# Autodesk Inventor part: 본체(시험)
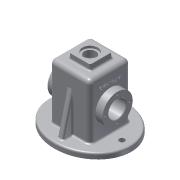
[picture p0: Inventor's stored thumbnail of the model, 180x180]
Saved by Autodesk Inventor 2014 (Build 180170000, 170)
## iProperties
Created: 2017-07
Part Number: 본체(시험)
Material: 알루미늄 6061
Document SubType Name: Modeling
Designer: 702-12
Density: 2.71 g/cm^3
Appearance: 알루미늄 - 평지
Mass: 893.713 g
Surface Area: 987.976 cm^2
Volume: 329.783 cm^3
Author: 702-12
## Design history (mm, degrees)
sketch "스케치1" dims "d0" = 75, "d1" = 65
  geometry: 2 further points; 1 other entity
  constraints: 1 coincident, 2 other
extrude "돌출1" new body sketch "스케치1" distance "d2" = 10; taper "d3" = 0 deg
sketch "스케치2"
  geometry: L1 (-37, -37)-(37, -37); L2 (37, -37)-(37, 37); L3 (37, 37)-(-37, 37); L4 (-37, 37)-(-37, -37); L5 (-37, -37)-(37, 37); L6 (37, -37)-(-37, 37); 1 further point; 1 other entity
  constraints: 12 end point, 2 midpoint, 2 parallel, 1 horizontal, 1 perpendicular, 1 other
  dimensions: "d4" = 74 distance of L3.end L2.end; "d5" = 74 distance of L2.end L1.end
extrude "돌출2" join sketch "스케치2" distance "d6" = 100; taper "d7" = 0 deg
sketch "스케치3"
  geometry: L1 (0, 74)-(-100, 74) reference; L2 (10, -28)-(10, 102) reference; C1 r 27.5 at (-45, 37); 1 further point
  constraints: 1 centre point
  dimensions: "d8" = 55 diameter of C1; "d9" = 55 distance from line of C1.centre L2; "d10" = 37 distance from line of L1 C1.centre
extrude "돌출3" join sketch "스케치3" distance "d11" = 13; taper "d12" = 0 deg
node "작업 평면1"
sketch "스케치4"
  geometry: L1 (65, 10)-(65, 0) reference; L2 (65, 0)-(-65, 0) reference; L3 (-65, 0)-(-65, 10) reference; L4 (-65, 10)-(-37, 10) reference; L5 (-37, 10)-(-37, 110) reference; L6 (-37, 110)-(37, 110) reference; L7 (37, 110)-(37, 10) reference; L8 (37, 10)-(65, 10) reference; L9 (-55, 10)-(-37, 82.194); L10 (-55, 10)-(8.14, 10); L11 (-37, 82.194)-(-37, 10); L12 (-55, 10)-(-37, 10); 1 further point
  constraints: 8 end point, 2 point on line, 1 collinear, 1 horizontal, 1 perpendicular
  dimensions: "d14" = 76 deg angle of L10 L9; "d15" = 10 distance of L3.end L9.start
extrude "돌출4" join sketch "스케치4" stored distance "d16" = 10; taper "d17" = 0 deg
node "작업 평면2"
sketch "스케치7"
  geometry: L1 (-32, -105)-(32, -105); L2 (32, -105)-(32, 105); L3 (32, 105)-(-32, 105); L4 (-32, 105)-(-32, -105); L5 (-32, -105)-(32, 105); L6 (32, -105)-(-32, 105); L7 (37, 110)-(-37, 110) reference; L8 (37, 10)-(37, 110) reference; 1 further point
  constraints: 12 end point, 2 midpoint, 2 parallel, 1 horizontal, 1 perpendicular
  dimensions: "d26" = 5 distance between parallel lines of L7 L3; "d27" = 5 distance between parallel lines of L8 L2
extrude "돌출7" cut sketch "스케치7" stored distance "d28" = 64; taper "d29" = 0 deg
sketch "스케치8"
  geometry: L1 (-37, 27.5)-(-50, 27.5) reference; L2 (-50, 27.5)-(-50, 82.5) reference; L3 (-50, 82.5)-(-37, 82.5) reference; L4 (-37, 82.5)-(-37, 110) reference; L5 (-37, 110)-(37, 110) reference; L6 (37, 110)-(37, 82.5) reference; L7 (37, 82.5)-(50, 82.5) reference; L8 (50, 82.5)-(50, 27.5) reference; L9 (50, 27.5)-(37, 27.5) reference; L10 (37, 27.5)-(37, 10) reference; L11 (37, 10)-(75, 10) reference; L12 (75, 10)-(75, 0) reference; L13 (75, 0)-(32, 0) reference; L14 (32, 0)-(32, 105) reference; L15 (32, 105)-(-32, 105) reference; L16 (-32, 105)-(-32, 0) reference; L17 (-32, 0)-(-75, 0) reference; L18 (-75, 0)-(-75, 10) reference; L19 (-75, 10)-(-37, 10) reference; L20 (-37, 10)-(-37, 27.5) reference; L21 (50, 55)-(-50, 55); L22 (32, 55)-(32, 82.5); L23 (32, 82.5)-(25, 75.5); L24 (32, 82.5)-(70.891, 82.5); L25 (25, 75.5)-(25, 55); L26 (0, 0)-(0, 105); L27 (-32, 82.5)-(-25, 75.5); L28 (-25, 75.5)-(-25, 55); L29 (-32, 55)-(-32, 82.5)
  constraints: 18 end point, 4 point on line, 4 symmetric about line, 3 midpoint, 1 horizontal, 1 perpendicular
  dimensions: "d31" = 27.5 distance of L22.start L22.end; "d32" = 135 deg angle of L23 L24
revolve "회전1" sketch "스케치8" stored, may be unused: angle "d34" = 90 deg
sketch "스케치10"
  geometry: C1 r 27.5 at (0, 0) reference; C2 r 16 at (0, 0); 1 further point
  constraints: 1 centre point, 1 coincident
  dimensions: "d38" = 32 diameter of C2
extrude "돌출9" cut sketch "스케치10" distance "d39" = 120; taper "d40" = 0 deg
sketch "스케치11"
  geometry: 5 further points
hole "구멍1" sketch "스케치11" at (-22.5, 0), (0, 22.5), (22.5, 0), (0, -22.5) diameter "d42" = 3.242; stored, may be unused: countersink angle "d46" = 90 deg, drill point angle "d48" = 118 deg; dims "d43" = 8, "d44" = 4, "d45" = 2, "d47" = 10
fillet "모깎기1" dims "d49" = 8
fillet "모깎기2" dims "d50" = 8
fillet "모깎기5" dims "d53" = 3
fillet "모깎기6" dims "d54" = 3
fillet "모깎기7" dims "d55" = 3
fillet "모깎기8" dims "d56" = 3
fillet "모깎기9" dims "d57" = 3
sketch "스케치12"
  geometry: L1 (40, -29)-(40, 29) reference; L2 (29, 40)-(8, 40) reference; L3 (8, 40)-(8, 51.16) reference; L4 (2, 57.344)-(-2, 57.344) reference; L5 (-8, 51.16)-(-8, 40) reference; L6 (-8, 40)-(-29, 40) reference; L7 (-40, 29)-(-40, -29) reference; L8 (-29, -40)-(-8, -40) reference; L9 (-8, -40)-(-8, -51.16) reference; L10 (-2, -57.344)-(2, -57.344) reference; L11 (8, -51.16)-(8, -40) reference; L12 (8, -40)-(29, -40) reference; L13 (-32, -32)-(32, -32) reference; L14 (32, -32)-(32, 32) reference; L15 (32, 32)-(-32, 32) reference; L16 (-32, 32)-(-32, -32) reference; L17 (0, 0)-(-58, 0); L18 (0, 0)-(58, 0); C1 r 5 at (-58, 0); C2 r 5 at (58, 0); A1 r 11 centre (29, -29) between (29, -40) and (40, -29) reference; A2 r 11 centre (29, 29) between (40, 29) and (29, 40) reference; A3 r 11 centre (-29, 29) between (-29, 40) and (-40, 29) reference; A4 r 11 centre (-29, -29) between (-40, -29) and (-29, -40) reference; 1 further point
  constraints: 4 end point, 2 centre point, 2 coincident, 1 collinear, 1 perpendicular, 5 other
  dimensions: "d58" = 58 distance of L17.start L17.end; "d59" = 10 diameter of C1; "d60" = 58 distance of L17.start L18.end; "d61" = 10 diameter of C2
extrude "돌출10" cut sketch "스케치12" distance "d62" = 120; taper "d63" = 0 deg
fillet "모깎기12" dims "d66" = 0.5
chamfer "모따기1" distance "d67" = 1; stored, may be unused: second distance "d68" = 2, angle "d69" = 45 deg
node "작업 평면3"
sketch "스케치13"
  geometry: L1 (-72, 10)-(-63, 10) reference; L2 (-63, 10)-(-63, 0) reference; L3 (-63, 0)-(-75, 0) reference; L4 (-75, 0)-(-75, 7) reference; L5 (75, 7)-(75, 0) reference; L6 (75, 0)-(63, 0) reference; L7 (63, 0)-(63, 10) reference; L8 (63, 10)-(72, 10) reference; L9 (39.026, 32.5)-(40, 30.879) reference; L10 (40, 30.879)-(50, 30.879) reference; L11 (50, 30.879)-(50, 27.5) reference; L12 (50, 27.5)-(37.5, 27.5) reference; L13 (37, 27)-(37, 13) reference; L14 (40, 10)-(53, 10) reference; L15 (53, 10)-(53, 0) reference; L16 (53, 0)-(32, 0) reference; L17 (32, 0)-(32, 27.293) reference; L18 (31.854, 27.646)-(25.146, 34.354) reference; L19 (25, 34.707)-(25, 39) reference; L20 (25, 39)-(49, 39) reference; L21 (49, 39)-(50, 38) reference; L22 (50, 38)-(50, 34.121) reference; L23 (50, 34.121)-(40, 34.121) reference; L24 (40, 34.121)-(39.026, 32.5) reference; L25 (-40, 30.879)-(-39.026, 32.5) reference; L26 (-39.026, 32.5)-(-40, 34.121) reference; L27 (-40, 34.121)-(-50, 34.121) reference; L28 (-50, 34.121)-(-50, 38) reference; L29 (-50, 38)-(-49, 39) reference; L30 (-49, 39)-(-25, 39) reference; L31 (-25, 39)-(-25, 34.707) reference; L32 (-25.146, 34.354)-(-31.854, 27.646) reference; L33 (-32, 27.293)-(-32, 0) reference; L34 (-32, 0)-(-53, 0) reference; L35 (-53, 0)-(-53, 10) reference; L36 (-53, 10)-(-40, 10) reference; L37 (-37, 13)-(-37, 27) reference; L38 (-37.5, 27.5)-(-50, 27.5) reference; L39 (-50, 27.5)-(-50, 30.879) reference; L40 (-50, 30.879)-(-40, 30.879) reference; L41 (-40, 75.879)-(-39.026, 77.5) reference; L42 (-39.026, 77.5)-(-40, 79.121) reference; L43 (-40, 79.121)-(-50, 79.121) reference; L44 (-50, 79.121)-(-50, 82.5) reference; L45 (-50, 82.5)-(-37.5, 82.5) reference; L46 (-37, 83)-(-37, 102) reference; L47 (-29, 110)-(29, 110) reference; L48 (37, 102)-(37, 83) reference; L49 (37.5, 82.5)-(50, 82.5) reference; L50 (50, 82.5)-(50, 79.121) reference; L51 (50, 79.121)-(40, 79.121) reference; L52 (40, 79.121)-(39.026, 77.5) reference; L53 (39.026, 77.5)-(40, 75.879) reference; L54 (40, 75.879)-(50, 75.879) reference; L55 (50, 75.879)-(50, 72) reference; L56 (50, 72)-(49, 71) reference; L57 (49, 71)-(25, 71) reference; L58 (25, 71)-(25, 75.293) reference; L59 (25.146, 75.646)-(31.854, 82.354) reference; L60 (32, 82.707)-(32, 105) reference; L61 (32, 105)-(-32, 105) reference; L62 (-32, 105)-(-32, 82.707) reference; L63 (-31.854, 82.354)-(-25.146, 75.646) reference; L64 (-25, 75.293)-(-25, 71) reference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; A1 r 0.5 centre (37.5, 27) between (37.5, 27.5) and (37, 27) reference; A2 r 3 centre (40, 13) between (37, 13) and (40, 10) reference; A3 r 0.5 centre (31.5, 27.293) between (32, 27.293) and (31.854, 27.646) reference; A4 r 0.5 centre (25.5, 34.707) between (25, 34.707) and (25.146, 34.354) reference; A5 r 0.5 centre (-25.5, 34.707) between (-25.146, 34.354) and (-25, 34.707) reference; A6 r 0.5 centre (-31.5, 27.293) between (-31.854, 27.646) and (-32, 27.293) reference; A7 r 3 centre (-40, 13) between (-40, 10) and (-37, 13) reference; A8 r 0.5 centre (-37.5, 27) between (-37, 27) and (-37.5, 27.5) reference; A9 r 0.5 centre (-37.5, 83) between (-37.5, 82.5) and (-37, 83) reference; A10 r 8 centre (-29, 102) between (-29, 110) and (-37, 102) reference; A11 r 8 centre (29, 102) between (37, 102) and (29, 110) reference; A12 r 0.5 centre (37.5, 83) between (37, 83) and (37.5, 82.5) reference; A13 r 0.5 centre (25.5, 75.293) between (25.146, 75.646) and (25, 75.293) reference; A14 r 0.5 centre (31.5, 82.707) between (31.854, 82.354) and (32, 82.707) reference; A15 r 0.5 centre (-31.5, 82.707) between (-32, 82.707) and (-31.854, 82.354) reference; A16 r 0.5 centre (-25.5, 75.293) between (-25, 75.293) and (-25.146, 75.646) reference; 1 further point
  constraints: 8 end point, 2 point on line, 2 other
  dimensions: "d74" = 40 distance of L70.end L71.end; "d94" = 5 deg angle of L46 L70
extrude "돌출11" join sketch "스케치13" stored distance "d76" = 40; taper "d77" = 0 deg
fillet "모깎기13" dims "d78" = 3
fillet "모깎기14" dims "d79" = 3
sketch "스케치14"
  geometry: C1 r 14 at (15.239, 20); 1 further point
  constraints: 1 centre point, 1 coincident
  dimensions: "d80" = 28 diameter of C1
extrude "돌출12" cut sketch "스케치14" distance "d81" = 4; taper "d82" = 0 deg
sketch "스케치15"
  geometry: C1 r 14 at (0, 0) reference; C2 r 10.5 at (0, 0)
  constraints: 1 centre point, 1 coincident
  dimensions: "d83" = 21 diameter of C2
extrude "돌출13" cut sketch "스케치15" distance "d84" = 100; taper "d85" = 0 deg
fillet "모깎기16" dims "d87" = 3
fillet "모깎기17" dims "d88" = 3
node "작업 평면4"
sketch "스케치16"
  geometry: L1 (89, 66)-(0, 66) reference; L2 (-18, 46)-(-18, 12) reference; 2 further points
  constraints: 1 other
  dimensions: "d90" = 37 distance from line of L1 point (12, 29); "d91" = 30 distance from line of L2 point (12, 29)
feature "엠보싱1" sketch "스케치16" dims "d0" = 75, "d1" = 65, "d92" = 0.5, "d93" = 0
node "솔리드1"
mirror "대칭1"
mirror "대칭2"
mirror "대칭3"
mirror "대칭4"
node "절단 모서리 투영1"
node "절단 모서리 투영2"
node "절단 모서리 투영3"
node "절단 모서리 투영4"
other parameters: "d13" = 0, "d18" = 0, "d33" = 7, "d70" = 0, "d89" = 1
